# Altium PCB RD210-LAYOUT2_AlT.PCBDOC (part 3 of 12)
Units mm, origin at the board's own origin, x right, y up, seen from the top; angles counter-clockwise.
Board outline 250 x 123 mm, 4 copper layers (TOP, Mid-Layer 1, Mid-Layer 2, BOTTOM), stack 0.711 mm thick; 1043 components, 659 nets, 2786 pads, 1228 vias.
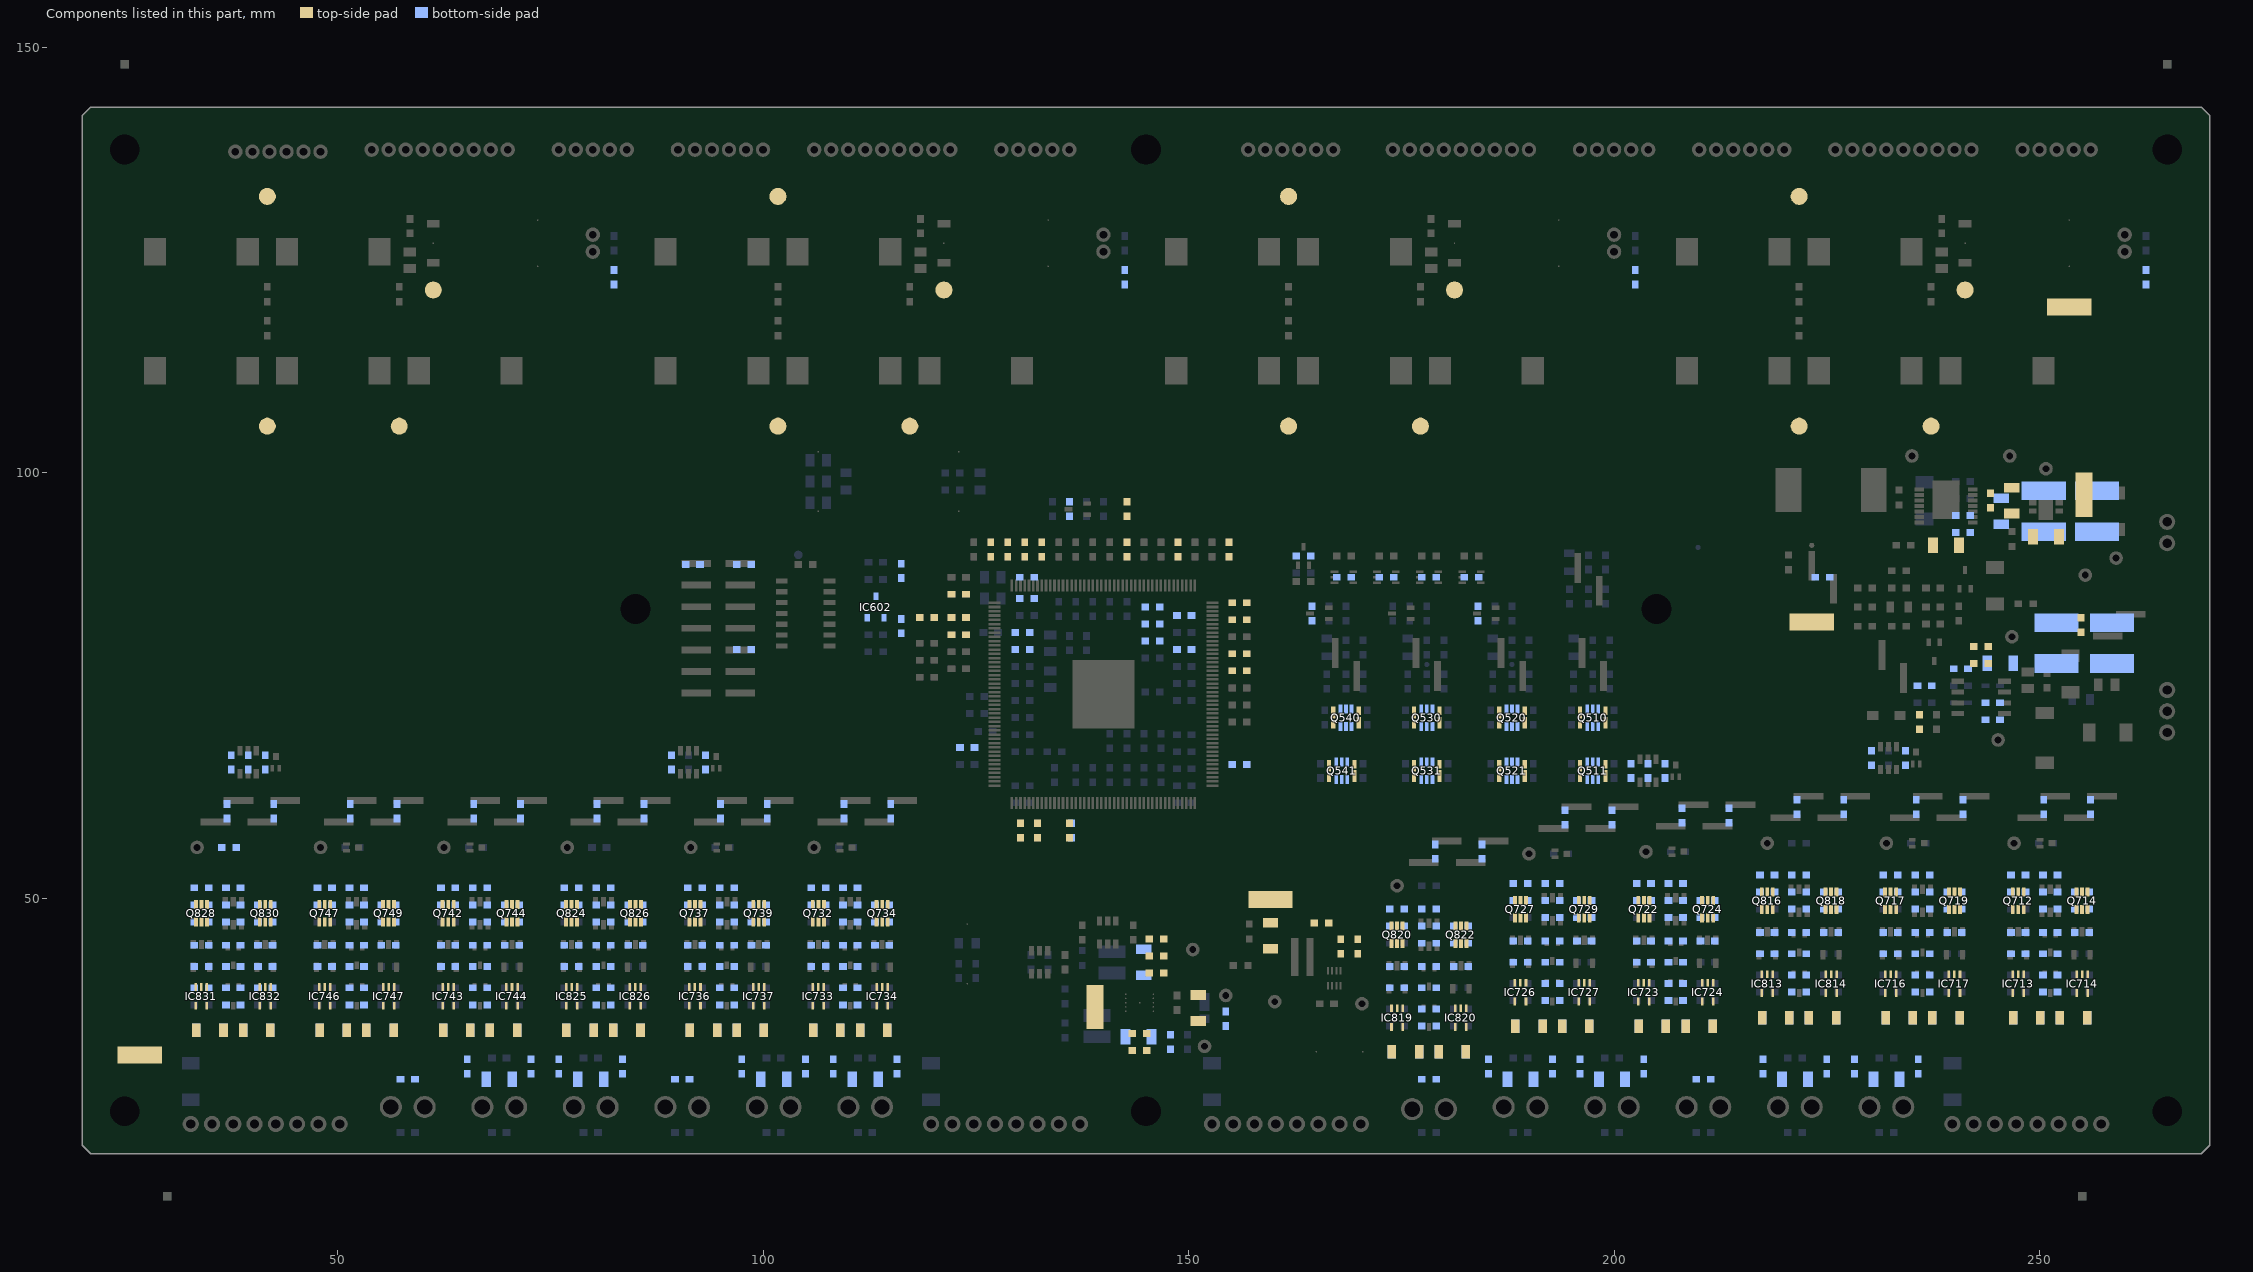
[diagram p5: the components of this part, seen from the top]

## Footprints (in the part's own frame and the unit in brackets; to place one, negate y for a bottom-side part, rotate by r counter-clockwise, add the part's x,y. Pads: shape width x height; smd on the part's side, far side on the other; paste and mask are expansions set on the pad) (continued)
_CGA3E2X7R1H104K080AA_+57 [mm] "KC00080BKP"
  rect 0.9x0.8 smd paste-0.9 mask+0: 1(0.85,0) 2(-0.85,0)
_CGA3E2X7R1H104K080AA_+58 [mm] "KC00080BKP"
  rect 0.9x0.8 smd paste-0.9 mask+0: 1(0.85,0) 2(-0.85,0)
_CGA3E2X7R1H104K080AA_+59 [mm] "KC00080BKP"
  rect 0.9x0.8 smd paste-0.9 mask+0: 1(0.85,0) 2(-0.85,0)
_CGA3E2X7R1H104K080AA_+60 [mm] "KC00080BKP"
  rect 0.9x0.8 smd paste-0.9 mask+0: 1(0.85,0) 2(-0.85,0)
_CGA3E2X7R1H104K080AA_+61 [mm] "KC00080BKP"
  rect 0.9x0.8 smd paste-0.9 mask+0: 1(0.85,0) 2(-0.85,0)
_CGA3E2X7R1H104K080AA_+62 [mm] "KC00080BKP"
  rect 0.9x0.8 smd paste-0.9 mask+0: 1(0.85,0) 2(-0.85,0)
_CGA3E2X7R1H104K080AA_+63 [mm] "KC00080BKP"
  rect 0.9x0.8 smd paste-0.9 mask+0: 1(0.85,0) 2(-0.85,0)
_CGA5H2C0G1H473J115AA_ [mm] "KC00080BKP"
  rect 1.15x1.8 smd paste-1.8 mask+0: 1(1.525,0) 2(-1.525,0)
_CGA5H2C0G1H473J115AA_+1 [mm] "KC00080BKP"
  rect 1.15x1.8 smd paste-1.8 mask+0: 1(1.525,0) 2(-1.525,0)
_CGA5H2C0G1H473J115AA_+2 [mm] "KC00080BKP"
  rect 1.15x1.8 smd paste-1.8 mask+0: 1(1.525,0) 2(-1.525,0)
_CGA5H2C0G1H473J115AA_+3 [mm] "KC00080BKP"
  rect 1.15x1.8 smd paste-1.8 mask+0: 1(1.525,0) 2(-1.525,0)
_CGA5H2C0G1H473J115AA_+4 [mm] "KC00080BKP"
  rect 1.15x1.8 smd paste-1.8 mask+0: 1(1.525,0) 2(-1.525,0)
_CGA5H2C0G1H473J115AA_+5 [mm] "KC00080BKP"
  rect 1.15x1.8 smd paste-1.8 mask+0: 1(1.525,0) 2(-1.525,0)
_CGA5H2C0G1H473J115AA_+6 [mm] "KC00080BKP"
  rect 1.15x1.8 smd paste-1.8 mask+0: 1(1.525,0) 2(-1.525,0)
_CGA5H2C0G1H473J115AA_+7 [mm] "KC00080BKP"
  rect 1.15x1.8 smd paste-1.8 mask+0: 1(1.525,0) 2(-1.525,0)
_CGA5L1X7R0J226M160AC_ [mm] "KC00080BKP"
  rect 1.15x1.8 smd paste-1.8 mask+0: 1(1.525,0) 2(-1.525,0)
_CGA5L1X7R0J226M160AC_+1 [mm] "KC00080BKP"
  rect 1.15x1.8 smd paste-1.8 mask+0: 1(1.525,0) 2(-1.525,0)
_CGA5L1X7R0J226M160AC_+2 [mm] "KC00080BKP"
  rect 1.15x1.8 smd paste-1.8 mask+0: 1(-1.525,0) 2(1.525,0)
_CGA5L1X7R1H106K160AC_ [mm] "KC00080BKP"
  rect 1.15x1.8 smd paste-1.8 mask+0: 1(-1.525,0) 2(1.525,0)
_CGA5L1X7R1H106K160AC_+1 [mm] "KC00080BKP"
  rect 1.15x1.8 smd paste-1.8 mask+0: 1(-1.525,0) 2(1.525,0)
_CGA5L1X7R1H106K160AC_+2 [mm] "KC00080BKP"
  rect 1.15x1.8 smd paste-1.8 mask+0: 1(1.525,0) 2(-1.525,0)
_CGA5L1X7R1H106K160AC_+3 [mm] "KC00080BKP"
  rect 1.15x1.8 smd paste-1.8 mask+0: 1(-1.525,0) 2(1.525,0)
_CGA5L2X7R2A104K160AA_ [mm] "KC00080BKP"
  rect 1.15x1.8 smd paste-1.8 mask+0: 1(-1.525,0) 2(1.525,0)
_CGA5L2X7R2A104K160AA_+1 [mm] "KC00080BKP"
  rect 1.15x1.8 smd paste-1.8 mask+0: 1(1.525,0) 2(-1.525,0)
_CKG57NX7S2A226M500JJ_ [mm] "KC00080BKP"
  rect 2.2x5.2 smd paste-5.2 mask+0: 1(2.4,0) 2(-2.4,0)
_CKG57NX7S2A226M500JJ_+1 [mm] "KC00080BKP"
  rect 2.2x5.2 smd paste-5.2 mask+0: 1(2.4,0) 2(-2.4,0)
_CKG57NX7S2A226M500JJ_+2 [mm] "KC00080BKP"
  rect 2.2x5.2 smd paste-5.2 mask+0: 1(2.4,0) 2(-2.4,0)
_CKG57NX7S2A226M500JJ_+3 [mm] "KC00080BKP"
  rect 2.2x5.2 smd paste-5.2 mask+0: 1(2.4,0) 2(-2.4,0)
_Direct_In_PAD-D2_ [mm] "KC00080BKP"
  round 2 smd paste-2 mask+0: 1(0,0)
_Direct_In_PAD-D2_+1 [mm] "KC00080BKP"
  round 2 smd paste-2 mask+0: 1(0,0)
_Direct_In_PAD-D2_+2 [mm] "KC00080BKP"
  round 2 smd paste-2 mask+0: 1(0,0)
_Direct_In_PAD-D2_+3 [mm] "KC00080BKP"
  round 2 smd paste-2 mask+0: 1(0,0)
_Direct_In_PAD-D2_+4 [mm] "KC00080BKP"
  round 2 smd paste-2 mask+0: 1(0,0)
_Direct_In_PAD-D2_+5 [mm] "KC00080BKP"
  round 2 smd paste-2 mask+0: 1(0,0)
_Direct_In_PAD-D2_+6 [mm] "KC00080BKP"
  round 2 smd paste-2 mask+0: 1(0,0)
_Direct_In_PAD-D2_+7 [mm] "KC00080BKP"
  round 2 smd paste-2 mask+0: 1(0,0)
_Direct_In_PAD-D2_+8 [mm] "KC00080BKP"
  round 2 smd paste-2 mask+0: 1(0,0)
_Direct_In_PAD-D2_+9 [mm] "KC00080BKP"
  round 2 smd paste-2 mask+0: 1(0,0)
_Direct_In_PAD-D2_+10 [mm] "KC00080BKP"
  round 2 smd paste-2 mask+0: 1(0,0)
_Direct_In_PAD-D2_+11 [mm] "KC00080BKP"
  round 2 smd paste-2 mask+0: 1(0,0)
_Direct_In_PAD-D2_+12 [mm] "KC00080BKP"
  round 2 smd paste-2 mask+0: 1(0,0)
_Direct_In_PAD-D2_+13 [mm] "KC00080BKP"
  round 2 smd paste-2 mask+0: 1(0,0)
_Direct_In_PAD-D2_+14 [mm] "KC00080BKP"
  round 2 smd paste-2 mask+0: 1(0,0)
_Direct_In_PAD-D2_+15 [mm] "KC00080BKP"
  round 2 smd paste-2 mask+0: 1(0,0)
_HW-1-S_ [mm] "KC00080BKP"
  rect 5.2x2 smd paste-5.2 mask+0: 1(0,0)
_HW-1-S_+1 [mm] "KC00080BKP"
  rect 5.2x2 smd paste-5.2 mask+0: 1(0,0)
_HW-1-S_+2 [mm] "KC00080BKP"
  rect 5.2x2 smd paste-5.2 mask+0: 1(0,0)
_HW-1-S_+3 [mm] "KC00080BKP"
  rect 5.2x2 smd paste-5.2 mask+0: 1(0,0)
_HW-1-S_+4 [mm] "KC00080BKP"
  rect 5.2x2 smd paste-5.2 mask+0: 1(0,0)
_HW-1-S_+5 [mm] "KC00080BKP"
  rect 5.2x2 smd paste-5.2 mask+0: 1(0,0)
_INA290A2QDCKRQ1_ [mm] "KC00080BKP"
  rect 0.3x0.9 smd paste-0.9 mask+0: 1(-0.65,-1.1) 2(0,-1.1) 3(0.65,-1.1) 4(0.65,1.1) 5(-0.65,1.1)
_INA290A2QDCKRQ1_+1 [mm] "KC00080BKP"
  rect 0.3x0.9 smd paste-0.9 mask+0: 1(-0.65,-1.1) 2(0,-1.1) 3(0.65,-1.1) 4(0.65,1.1) 5(-0.65,1.1)
_INA290A2QDCKRQ1_+2 [mm] "KC00080BKP"
  rect 0.3x0.9 smd paste-0.9 mask+0: 1(-0.65,-1.1) 2(0,-1.1) 3(0.65,-1.1) 4(0.65,1.1) 5(-0.65,1.1)
_INA290A2QDCKRQ1_+3 [mm] "KC00080BKP"
  rect 0.3x0.9 smd paste-0.9 mask+0: 1(-0.65,-1.1) 2(0,-1.1) 3(0.65,-1.1) 4(0.65,1.1) 5(-0.65,1.1)
_INA290A2QDCKRQ1_+4 [mm] "KC00080BKP"
  rect 0.3x0.9 smd paste-0.9 mask+0: 1(-0.65,-1.1) 2(0,-1.1) 3(0.65,-1.1) 4(0.65,1.1) 5(-0.65,1.1)
_INA290A2QDCKRQ1_+5 [mm] "KC00080BKP"
  rect 0.3x0.9 smd paste-0.9 mask+0: 1(-0.65,-1.1) 2(0,-1.1) 3(0.65,-1.1) 4(0.65,1.1) 5(-0.65,1.1)
_INA290A2QDCKRQ1_+6 [mm] "KC00080BKP"
  rect 0.3x0.9 smd paste-0.9 mask+0: 1(-0.65,-1.1) 2(0,-1.1) 3(0.65,-1.1) 4(0.65,1.1) 5(-0.65,1.1)
_INA290A2QDCKRQ1_+7 [mm] "KC00080BKP"
  rect 0.3x0.9 smd paste-0.9 mask+0: 1(-0.65,-1.1) 2(0,-1.1) 3(0.65,-1.1) 4(0.65,1.1) 5(-0.65,1.1)
_INA290A2QDCKRQ1_+8 [mm] "KC00080BKP"
  rect 0.3x0.9 smd paste-0.9 mask+0: 1(-0.65,-1.1) 2(0,-1.1) 3(0.65,-1.1) 4(0.65,1.1) 5(-0.65,1.1)
_INA290A2QDCKRQ1_+9 [mm] "KC00080BKP"
  rect 0.3x0.9 smd paste-0.9 mask+0: 1(-0.65,-1.1) 2(0,-1.1) 3(0.65,-1.1) 4(0.65,1.1) 5(-0.65,1.1)
_INA290A2QDCKRQ1_+10 [mm] "KC00080BKP"
  rect 0.3x0.9 smd paste-0.9 mask+0: 1(-0.65,-1.1) 2(0,-1.1) 3(0.65,-1.1) 4(0.65,1.1) 5(-0.65,1.1)
_INA290A2QDCKRQ1_+11 [mm] "KC00080BKP"
  rect 0.3x0.9 smd paste-0.9 mask+0: 1(-0.65,-1.1) 2(0,-1.1) 3(0.65,-1.1) 4(0.65,1.1) 5(-0.65,1.1)
_INA290A2QDCKRQ1_+12 [mm] "KC00080BKP"
  rect 0.3x0.9 smd paste-0.9 mask+0: 1(-0.65,-1.1) 2(0,-1.1) 3(0.65,-1.1) 4(0.65,1.1) 5(-0.65,1.1)
_INA290A2QDCKRQ1_+13 [mm] "KC00080BKP"
  rect 0.3x0.9 smd paste-0.9 mask+0: 1(-0.65,-1.1) 2(0,-1.1) 3(0.65,-1.1) 4(0.65,1.1) 5(-0.65,1.1)
_INA290A2QDCKRQ1_+14 [mm] "KC00080BKP"
  rect 0.3x0.9 smd paste-0.9 mask+0: 1(-0.65,-1.1) 2(0,-1.1) 3(0.65,-1.1) 4(0.65,1.1) 5(-0.65,1.1)
_INA290A2QDCKRQ1_+15 [mm] "KC00080BKP"
  rect 0.3x0.9 smd paste-0.9 mask+0: 1(-0.65,-1.1) 2(0,-1.1) 3(0.65,-1.1) 4(0.65,1.1) 5(-0.65,1.1)
_INA290A2QDCKRQ1_+16 [mm] "KC00080BKP"
  rect 0.3x0.9 smd paste-0.9 mask+0: 1(-0.65,-1.1) 2(0,-1.1) 3(0.65,-1.1) 4(0.65,1.1) 5(-0.65,1.1)
_INA290A2QDCKRQ1_+17 [mm] "KC00080BKP"
  rect 0.3x0.9 smd paste-0.9 mask+0: 1(-0.65,-1.1) 2(0,-1.1) 3(0.65,-1.1) 4(0.65,1.1) 5(-0.65,1.1)
_INA290A2QDCKRQ1_+18 [mm] "KC00080BKP"
  rect 0.3x0.9 smd paste-0.9 mask+0: 1(-0.65,-1.1) 2(0,-1.1) 3(0.65,-1.1) 4(0.65,1.1) 5(-0.65,1.1)
_INA290A2QDCKRQ1_+19 [mm] "KC00080BKP"
  rect 0.3x0.9 smd paste-0.9 mask+0: 1(-0.65,-1.1) 2(0,-1.1) 3(0.65,-1.1) 4(0.65,1.1) 5(-0.65,1.1)
_INA290A2QDCKRQ1_+20 [mm] "KC00080BKP"
  rect 0.3x0.9 smd paste-0.9 mask+0: 1(-0.65,-1.1) 2(0,-1.1) 3(0.65,-1.1) 4(0.65,1.1) 5(-0.65,1.1)
_INA290A2QDCKRQ1_+21 [mm] "KC00080BKP"
  rect 0.3x0.9 smd paste-0.9 mask+0: 1(-0.65,-1.1) 2(0,-1.1) 3(0.65,-1.1) 4(0.65,1.1) 5(-0.65,1.1)
_INA290A2QDCKRQ1_+22 [mm] "KC00080BKP"
  rect 0.3x0.9 smd paste-0.9 mask+0: 1(-0.65,-1.1) 2(0,-1.1) 3(0.65,-1.1) 4(0.65,1.1) 5(-0.65,1.1)
_INA290A2QDCKRQ1_+23 [mm] "KC00080BKP"
  rect 0.3x0.9 smd paste-0.9 mask+0: 1(-0.65,-1.1) 2(0,-1.1) 3(0.65,-1.1) 4(0.65,1.1) 5(-0.65,1.1)
_KB_DELPS2.12_ [mm] "KC00080BKP"
  rect 1.4x0.5 smd paste-1.4 mask+0: 1(-0.6,0)
  rect 1x0.5 smd paste-1 mask+0: 2(0.8,0)
_KB_DELPS2.12_+1 [mm] "KC00080BKP"
  rect 1.4x0.5 smd paste-1.4 mask+0: 1(-0.6,0)
  rect 1x0.5 smd paste-1 mask+0: 2(0.8,0)
_KB_DELPS2.12_+2 [mm] "KC00080BKP"
  rect 1.4x0.5 smd paste-1.4 mask+0: 1(-0.6,0)
  rect 1x0.5 smd paste-1 mask+0: 2(0.8,0)
_KB_DELPS2.12_+3 [mm] "KC00080BKP"
  rect 1.4x0.5 smd paste-1.4 mask+0: 1(-0.6,0)
  rect 1x0.5 smd paste-1 mask+0: 2(0.8,0)
_KS_DELPS1.22_ [mm] "KC00080BKP"
  rect 1.4x0.5 smd paste-1.4 mask+0: 1(-0.6,0)
  rect 1x0.5 smd paste-1 mask+0: 2(0.8,0)
_KS_DELPS1.22_+1 [mm] "KC00080BKP"
  rect 1.4x0.5 smd paste-1.4 mask+0: 1(-0.6,0)
  rect 1x0.5 smd paste-1 mask+0: 2(0.8,0)
_KS_DELPS1.22_+2 [mm] "KC00080BKP"
  rect 1.4x0.5 smd paste-1.4 mask+0: 1(-0.6,0)
  rect 1x0.5 smd paste-1 mask+0: 2(0.8,0)
_KS_DELPS1.22_+3 [mm] "KC00080BKP"
  rect 1.4x0.5 smd paste-1.4 mask+0: 1(-0.6,0)
  rect 1x0.5 smd paste-1 mask+0: 2(0.8,0)
_KT_DELQS1.12_ [mm] "KC00080BKP"
  rect 1.4x0.5 smd paste-1.4 mask+0: 1(-0.6,0)
  rect 1x0.5 smd paste-1 mask+0: 2(0.8,0)
_KT_DELQS1.12_+1 [mm] "KC00080BKP"
  rect 1.4x0.5 smd paste-1.4 mask+0: 1(-0.6,0)
  rect 1x0.5 smd paste-1 mask+0: 2(0.8,0)
_KT_DELQS1.12_+2 [mm] "KC00080BKP"
  rect 1.4x0.5 smd paste-1.4 mask+0: 1(-0.6,0)
  rect 1x0.5 smd paste-1 mask+0: 2(0.8,0)
_KT_DELQS1.12_+3 [mm] "KC00080BKP"
  rect 1.4x0.5 smd paste-1.4 mask+0: 1(-0.6,0)
  rect 1x0.5 smd paste-1 mask+0: 2(0.8,0)
_KT_DELQS1.12_+4 [mm] "KC00080BKP"
  rect 1.4x0.5 smd paste-1.4 mask+0: 1(-0.6,0)
  rect 1x0.5 smd paste-1 mask+0: 2(0.8,0)
_KT_DELQS1.12_+5 [mm] "KC00080BKP"
  rect 1.4x0.5 smd paste-1.4 mask+0: 1(-0.6,0)
  rect 1x0.5 smd paste-1 mask+0: 2(0.8,0)
_KT_DELQS1.12_+6 [mm] "KC00080BKP"
  rect 1.4x0.5 smd paste-1.4 mask+0: 1(-0.6,0)
  rect 1x0.5 smd paste-1 mask+0: 2(0.8,0)
_KT_DELQS1.12_+7 [mm] "KC00080BKP"
  rect 1.4x0.5 smd paste-1.4 mask+0: 1(-0.6,0)
  rect 1x0.5 smd paste-1 mask+0: 2(0.8,0)
_LM4040QCEM3-3.0_ [mm] "KC00080BKP"
  rect 0.6x0.9 smd paste-0.9 mask+0: 1(0.95,1.25) 2(-1,1.25) 3(0,-1.25)
_RK73B1JTTD1R0J_ [mm] "KC00080BKP"
  rect 0.9x0.8 smd paste-0.9 mask+0: 1(0.85,0) 2(-0.85,0)
_RK73B1JTTD1R0J_+1 [mm] "KC00080BKP"
  rect 0.9x0.8 smd paste-0.9 mask+0: 1(0.85,0) 2(-0.85,0)
_RK73B1JTTD1R0J_+2 [mm] "KC00080BKP"
  rect 0.9x0.8 smd paste-0.9 mask+0: 1(0.85,0) 2(-0.85,0)
_RK73B1JTTD1R0J_+3 [mm] "KC00080BKP"
  rect 0.9x0.8 smd paste-0.9 mask+0: 1(0.85,0) 2(-0.85,0)
_RK73B1JTTD103J_ [mm] "KC00080BKP"
  rect 0.9x0.8 smd paste-0.9 mask+0: 1(0.85,0) 2(-0.85,0)
_RK73B1JTTD103J_+1 [mm] "KC00080BKP"
  rect 0.9x0.8 smd paste-0.9 mask+0: 1(0.85,0) 2(-0.85,0)
_RK73B1JTTD103J_+2 [mm] "KC00080BKP"
  rect 0.9x0.8 smd paste-0.9 mask+0: 1(0.85,0) 2(-0.85,0)
_RK73B1JTTD103J_+3 [mm] "KC00080BKP"
  rect 0.9x0.8 smd paste-0.9 mask+0: 1(0.85,0) 2(-0.85,0)
_RK73B1JTTD103J_+4 [mm] "KC00080BKP"
  rect 0.9x0.8 smd paste-0.9 mask+0: 1(0.85,0) 2(-0.85,0)
_RK73B1JTTD103J_+5 [mm] "KC00080BKP"
  rect 0.9x0.8 smd paste-0.9 mask+0: 1(0.85,0) 2(-0.85,0)
_RK73B1JTTD103J_+6 [mm] "KC00080BKP"
  rect 0.9x0.8 smd paste-0.9 mask+0: 1(0.85,0) 2(-0.85,0)
_RK73B1JTTD103J_+7 [mm] "KC00080BKP"
  rect 0.9x0.8 smd paste-0.9 mask+0: 1(0.85,0) 2(-0.85,0)
_RK73B1JTTD103J_+8 [mm] "KC00080BKP"
  rect 0.9x0.8 smd paste-0.9 mask+0: 1(0.85,0) 2(-0.85,0)
_RK73B1JTTD103J_+9 [mm] "KC00080BKP"
  rect 0.9x0.8 smd paste-0.9 mask+0: 1(0.85,0) 2(-0.85,0)
_RK73B1JTTD103J_+10 [mm] "KC00080BKP"
  rect 0.9x0.8 smd paste-0.9 mask+0: 1(0.85,0) 2(-0.85,0)
_RK73B1JTTD103J_+11 [mm] "KC00080BKP"
  rect 0.9x0.8 smd paste-0.9 mask+0: 1(0.85,0) 2(-0.85,0)
_RK73B1JTTD103J_+12 [mm] "KC00080BKP"
  rect 0.9x0.8 smd paste-0.9 mask+0: 1(0.85,0) 2(-0.85,0)
_RK73B1JTTD103J_+13 [mm] "KC00080BKP"
  rect 0.9x0.8 smd paste-0.9 mask+0: 1(0.85,0) 2(-0.85,0)
_RK73B1JTTD103J_+14 [mm] "KC00080BKP"
  rect 0.9x0.8 smd paste-0.9 mask+0: 1(0.85,0) 2(-0.85,0)
_RK73B1JTTD103J_+15 [mm] "KC00080BKP"
  rect 0.9x0.8 smd paste-0.9 mask+0: 1(0.85,0) 2(-0.85,0)
_RK73B1JTTD103J_+16 [mm] "KC00080BKP"
  rect 0.9x0.8 smd paste-0.9 mask+0: 1(0.85,0) 2(-0.85,0)
_RK73B1JTTD103J_+17 [mm] "KC00080BKP"
  rect 0.9x0.8 smd paste-0.9 mask+0: 1(0.85,0) 2(-0.85,0)
_RK73B1JTTD103J_+18 [mm] "KC00080BKP"
  rect 0.9x0.8 smd paste-0.9 mask+0: 1(0.85,0) 2(-0.85,0)
_RK73B1JTTD103J_+19 [mm] "KC00080BKP"
  rect 0.9x0.8 smd paste-0.9 mask+0: 1(0.85,0) 2(-0.85,0)
_RK73B1JTTD103J_+20 [mm] "KC00080BKP"
  rect 0.9x0.8 smd paste-0.9 mask+0: 1(0.85,0) 2(-0.85,0)
_RK73B1JTTD103J_+21 [mm] "KC00080BKP"
  rect 0.9x0.8 smd paste-0.9 mask+0: 1(0.85,0) 2(-0.85,0)
_RK73B1JTTD103J_+22 [mm] "KC00080BKP"
  rect 0.9x0.8 smd paste-0.9 mask+0: 1(0.85,0) 2(-0.85,0)
_RK73B1JTTD103J_+23 [mm] "KC00080BKP"
  rect 0.9x0.8 smd paste-0.9 mask+0: 1(0.85,0) 2(-0.85,0)
_RK73B2BTTD100J_ [mm] "KC00080BKP"
  rect 1x1.6 smd paste-1.6 mask+0: 1(-1.6,0) 2(1.6,0)
_RK73B2BTTD100J_+1 [mm] "KC00080BKP"
  rect 1x1.6 smd paste-1.6 mask+0: 1(-1.6,0) 2(1.6,0)
_RK73B2BTTD100J_+2 [mm] "KC00080BKP"
  rect 1x1.6 smd paste-1.6 mask+0: 1(-1.6,0) 2(1.6,0)
_RK73B2BTTD100J_+3 [mm] "KC00080BKP"
  rect 1x1.6 smd paste-1.6 mask+0: 1(-1.6,0) 2(1.6,0)
_RK73B2BTTD100J_+4 [mm] "KC00080BKP"
  rect 1x1.6 smd paste-1.6 mask+0: 1(-1.6,0) 2(1.6,0)
_RK73B2BTTD100J_+5 [mm] "KC00080BKP"
  rect 1x1.6 smd paste-1.6 mask+0: 1(-1.6,0) 2(1.6,0)
_RK73B2BTTD100J_+6 [mm] "KC00080BKP"
  rect 1x1.6 smd paste-1.6 mask+0: 1(-1.6,0) 2(1.6,0)
_RK73B2BTTD100J_+7 [mm] "KC00080BKP"
  rect 1x1.6 smd paste-1.6 mask+0: 1(-1.6,0) 2(1.6,0)
_RK73B2BTTD100J_+8 [mm] "KC00080BKP"
  rect 1x1.6 smd paste-1.6 mask+0: 1(-1.6,0) 2(1.6,0)
_RK73B2BTTD100J_+9 [mm] "KC00080BKP"
  rect 1x1.6 smd paste-1.6 mask+0: 1(-1.6,0) 2(1.6,0)
_RK73B2BTTD100J_+10 [mm] "KC00080BKP"
  rect 1x1.6 smd paste-1.6 mask+0: 1(-1.6,0) 2(1.6,0)
_RK73B2BTTD100J_+11 [mm] "KC00080BKP"
  rect 1x1.6 smd paste-1.6 mask+0: 1(-1.6,0) 2(1.6,0)
_RK73B2BTTD100J_+12 [mm] "KC00080BKP"
  rect 1x1.6 smd paste-1.6 mask+0: 1(-1.6,0) 2(1.6,0)
_RK73B2BTTD100J_+13 [mm] "KC00080BKP"
  rect 1x1.6 smd paste-1.6 mask+0: 1(-1.6,0) 2(1.6,0)
_RK73B2BTTD100J_+14 [mm] "KC00080BKP"
  rect 1x1.6 smd paste-1.6 mask+0: 1(-1.6,0) 2(1.6,0)
_RK73B2BTTD100J_+15 [mm] "KC00080BKP"
  rect 1x1.6 smd paste-1.6 mask+0: 1(-1.6,0) 2(1.6,0)
_RK73B2BTTD100J_+16 [mm] "KC00080BKP"
  rect 1x1.6 smd paste-1.6 mask+0: 1(-1.6,0) 2(1.6,0)
_RK73B2BTTD100J_+17 [mm] "KC00080BKP"
  rect 1x1.6 smd paste-1.6 mask+0: 1(-1.6,0) 2(1.6,0)
_RK73B2BTTD100J_+18 [mm] "KC00080BKP"
  rect 1x1.6 smd paste-1.6 mask+0: 1(1.6,0) 2(-1.6,0)
_RK73B2BTTD100J_+19 [mm] "KC00080BKP"
  rect 1x1.6 smd paste-1.6 mask+0: 1(1.6,0) 2(-1.6,0)
_RK73B2BTTD100J_+20 [mm] "KC00080BKP"
  rect 1x1.6 smd paste-1.6 mask+0: 1(-1.6,0) 2(1.6,0)
_RK73B2BTTD100J_+21 [mm] "KC00080BKP"
  rect 1x1.6 smd paste-1.6 mask+0: 1(-1.6,0) 2(1.6,0)
_RK73B2BTTD100J_+22 [mm] "KC00080BKP"
  rect 1x1.6 smd paste-1.6 mask+0: 1(1.6,0) 2(-1.6,0)
_RK73B2BTTD100J_+23 [mm] "KC00080BKP"
  rect 1x1.6 smd paste-1.6 mask+0: 1(1.6,0) 2(-1.6,0)
_RK73B2BTTD100J_+24 [mm] "KC00080BKP"
  rect 1x1.6 smd paste-1.6 mask+0: 1(1.6,0) 2(-1.6,0)
_RK73B2BTTD100J_+25 [mm] "KC00080BKP"
  rect 1x1.6 smd paste-1.6 mask+0: 1(1.6,0) 2(-1.6,0)
_RK73B2BTTD100J_+26 [mm] "KC00080BKP"
  rect 1x1.6 smd paste-1.6 mask+0: 1(1.6,0) 2(-1.6,0)
_RK73B2BTTD100J_+27 [mm] "KC00080BKP"
  rect 1x1.6 smd paste-1.6 mask+0: 1(1.6,0) 2(-1.6,0)
_RK73B2BTTD100J_+28 [mm] "KC00080BKP"
  rect 1x1.6 smd paste-1.6 mask+0: 1(1.6,0) 2(-1.6,0)
_RK73B2BTTD100J_+29 [mm] "KC00080BKP"
  rect 1x1.6 smd paste-1.6 mask+0: 1(-1.6,0) 2(1.6,0)
_RK73B2BTTD100J_+30 [mm] "KC00080BKP"
  rect 1x1.6 smd paste-1.6 mask+0: 1(1.6,0) 2(-1.6,0)
_RK73B2BTTD100J_+31 [mm] "KC00080BKP"
  rect 1x1.6 smd paste-1.6 mask+0: 1(1.6,0) 2(-1.6,0)
_RK73B2BTTD100J_+32 [mm] "KC00080BKP"
  rect 1x1.6 smd paste-1.6 mask+0: 1(1.6,0) 2(-1.6,0)
_RK73B2BTTD100J_+33 [mm] "KC00080BKP"
  rect 1x1.6 smd paste-1.6 mask+0: 1(1.6,0) 2(-1.6,0)
_RK73B2BTTD100J_+34 [mm] "KC00080BKP"
  rect 1x1.6 smd paste-1.6 mask+0: 1(1.6,0) 2(-1.6,0)
_RK73B2BTTD100J_+35 [mm] "KC00080BKP"
  rect 1x1.6 smd paste-1.6 mask+0: 1(1.6,0) 2(-1.6,0)
_RK73B2BTTD100J_+36 [mm] "KC00080BKP"
  rect 1x1.6 smd paste-1.6 mask+0: 1(1.6,0) 2(-1.6,0)
_RK73B2BTTD100J_+37 [mm] "KC00080BKP"
  rect 1x1.6 smd paste-1.6 mask+0: 1(1.6,0) 2(-1.6,0)
_RK73B2BTTD100J_+38 [mm] "KC00080BKP"
  rect 1x1.6 smd paste-1.6 mask+0: 1(1.6,0) 2(-1.6,0)
_RK73B2BTTD100J_+39 [mm] "KC00080BKP"
  rect 1x1.6 smd paste-1.6 mask+0: 1(1.6,0) 2(-1.6,0)
_RK73B2BTTD100J_+40 [mm] "KC00080BKP"
  rect 1x1.6 smd paste-1.6 mask+0: 1(1.6,0) 2(-1.6,0)
_RK73B2BTTD100J_+41 [mm] "KC00080BKP"
  rect 1x1.6 smd paste-1.6 mask+0: 1(1.6,0) 2(-1.6,0)
_RK73B2BTTD100J_+42 [mm] "KC00080BKP"
  rect 1x1.6 smd paste-1.6 mask+0: 1(1.6,0) 2(-1.6,0)
_RK73B2BTTD100J_+43 [mm] "KC00080BKP"
  rect 1x1.6 smd paste-1.6 mask+0: 1(1.6,0) 2(-1.6,0)
_RK73B2BTTD100J_+44 [mm] "KC00080BKP"
  rect 1x1.6 smd paste-1.6 mask+0: 1(-1.6,0) 2(1.6,0)
_RK73B2BTTD100J_+45 [mm] "KC00080BKP"
  rect 1x1.6 smd paste-1.6 mask+0: 1(1.6,0) 2(-1.6,0)
_RK73B2BTTD100J_+46 [mm] "KC00080BKP"
  rect 1x1.6 smd paste-1.6 mask+0: 1(-1.6,0) 2(1.6,0)
_RK73B2BTTD100J_+47 [mm] "KC00080BKP"
  rect 1x1.6 smd paste-1.6 mask+0: 1(-1.6,0) 2(1.6,0)
_RK73G1JTTD10R0D_ [mm] "KC00080BKP"
  rect 0.9x0.8 smd paste-0.9 mask+0: 1(-0.85,0) 2(0.85,0)
_RK73G1JTTD10R0D_+1 [mm] "KC00080BKP"
  rect 0.9x0.8 smd paste-0.9 mask+0: 1(0.85,0) 2(-0.85,0)
_RK73H1JTTD10R0F_ [mm] "KC00080BKP"
  rect 0.9x0.8 smd paste-0.9 mask+0: 1(0.85,0) 2(-0.85,0)
_RK73H1JTTD10R0F_+1 [mm] "KC00080BKP"
  rect 0.9x0.8 smd paste-0.9 mask+0: 1(0.85,0) 2(-0.85,0)
_RK73H1JTTD10R0F_+2 [mm] "KC00080BKP"
  rect 0.9x0.8 smd paste-0.9 mask+0: 1(0.85,0) 2(-0.85,0)
_RK73H1JTTD10R0F_+3 [mm] "KC00080BKP"
  rect 0.9x0.8 smd paste-0.9 mask+0: 1(0.85,0) 2(-0.85,0)
_RK73H1JTTD10R0F_+4 [mm] "KC00080BKP"
  rect 0.9x0.8 smd paste-0.9 mask+0: 1(0.85,0) 2(-0.85,0)
_RK73H1JTTD10R0F_+5 [mm] "KC00080BKP"
  rect 0.9x0.8 smd paste-0.9 mask+0: 1(0.85,0) 2(-0.85,0)
_RK73H1JTTD10R0F_+6 [mm] "KC00080BKP"
  rect 0.9x0.8 smd paste-0.9 mask+0: 1(0.85,0) 2(-0.85,0)
_RK73H1JTTD10R0F_+7 [mm] "KC00080BKP"
  rect 0.9x0.8 smd paste-0.9 mask+0: 1(0.85,0) 2(-0.85,0)
_RK73H1JTTD10R0F_+8 [mm] "KC00080BKP"
  rect 0.9x0.8 smd paste-0.9 mask+0: 1(0.85,0) 2(-0.85,0)
_RK73H1JTTD10R0F_+9 [mm] "KC00080BKP"
  rect 0.9x0.8 smd paste-0.9 mask+0: 1(0.85,0) 2(-0.85,0)
_RK73H1JTTD10R0F_+10 [mm] "KC00080BKP"
  rect 0.9x0.8 smd paste-0.9 mask+0: 1(0.85,0) 2(-0.85,0)
_RK73H1JTTD10R0F_+11 [mm] "KC00080BKP"
  rect 0.9x0.8 smd paste-0.9 mask+0: 1(0.85,0) 2(-0.85,0)
_RK73H1JTTD47R0F_ [mm] "KC00080BKP"
  rect 0.9x0.8 smd paste-0.9 mask+0: 1(0.85,0) 2(-0.85,0)
_RK73H1JTTD47R0F_+1 [mm] "KC00080BKP"
  rect 0.9x0.8 smd paste-0.9 mask+0: 1(0.85,0) 2(-0.85,0)
_RK73H1JTTD47R0F_+2 [mm] "KC00080BKP"
  rect 0.9x0.8 smd paste-0.9 mask+0: 1(0.85,0) 2(-0.85,0)
_RK73H1JTTD47R0F_+3 [mm] "KC00080BKP"
  rect 0.9x0.8 smd paste-0.9 mask+0: 1(0.85,0) 2(-0.85,0)
_RK73H1JTTD47R0F_+4 [mm] "KC00080BKP"
  rect 0.9x0.8 smd paste-0.9 mask+0: 1(0.85,0) 2(-0.85,0)
_RK73H1JTTD47R0F_+5 [mm] "KC00080BKP"
  rect 0.9x0.8 smd paste-0.9 mask+0: 1(0.85,0) 2(-0.85,0)
_RK73H1JTTD47R0F_+6 [mm] "KC00080BKP"
  rect 0.9x0.8 smd paste-0.9 mask+0: 1(0.85,0) 2(-0.85,0)
_RK73H1JTTD47R0F_+7 [mm] "KC00080BKP"
  rect 0.9x0.8 smd paste-0.9 mask+0: 1(0.85,0) 2(-0.85,0)
_RK73H1JTTD47R0F_+8 [mm] "KC00080BKP"
  rect 0.9x0.8 smd paste-0.9 mask+0: 1(0.85,0) 2(-0.85,0)
_RK73H1JTTD47R0F_+9 [mm] "KC00080BKP"
  rect 0.9x0.8 smd paste-0.9 mask+0: 1(0.85,0) 2(-0.85,0)
_RK73H1JTTD47R0F_+10 [mm] "KC00080BKP"
  rect 0.9x0.8 smd paste-0.9 mask+0: 1(0.85,0) 2(-0.85,0)
_RK73H1JTTD47R0F_+11 [mm] "KC00080BKP"
  rect 0.9x0.8 smd paste-0.9 mask+0: 1(0.85,0) 2(-0.85,0)
_RK73H1JTTD47R0F_+12 [mm] "KC00080BKP"
  rect 0.9x0.8 smd paste-0.9 mask+0: 1(0.85,0) 2(-0.85,0)
_RK73H1JTTD47R0F_+13 [mm] "KC00080BKP"
  rect 0.9x0.8 smd paste-0.9 mask+0: 1(0.85,0) 2(-0.85,0)
_RK73H1JTTD47R0F_+14 [mm] "KC00080BKP"
  rect 0.9x0.8 smd paste-0.9 mask+0: 1(0.85,0) 2(-0.85,0)
_RK73H1JTTD47R0F_+15 [mm] "KC00080BKP"
  rect 0.9x0.8 smd paste-0.9 mask+0: 1(0.85,0) 2(-0.85,0)
_RK73H1JTTD47R0F_+16 [mm] "KC00080BKP"
  rect 0.9x0.8 smd paste-0.9 mask+0: 1(0.85,0) 2(-0.85,0)
_RK73H1JTTD47R0F_+17 [mm] "KC00080BKP"
  rect 0.9x0.8 smd paste-0.9 mask+0: 1(0.85,0) 2(-0.85,0)
_RK73H1JTTD47R0F_+18 [mm] "KC00080BKP"
  rect 0.9x0.8 smd paste-0.9 mask+0: 1(0.85,0) 2(-0.85,0)
_RK73H1JTTD47R0F_+19 [mm] "KC00080BKP"
  rect 0.9x0.8 smd paste-0.9 mask+0: 1(0.85,0) 2(-0.85,0)
_RK73H1JTTD47R0F_+20 [mm] "KC00080BKP"
  rect 0.9x0.8 smd paste-0.9 mask+0: 1(0.85,0) 2(-0.85,0)
_RK73H1JTTD47R0F_+21 [mm] "KC00080BKP"
  rect 0.9x0.8 smd paste-0.9 mask+0: 1(0.85,0) 2(-0.85,0)
_RK73H1JTTD47R0F_+22 [mm] "KC00080BKP"
  rect 0.9x0.8 smd paste-0.9 mask+0: 1(0.85,0) 2(-0.85,0)
_RK73H1JTTD47R0F_+23 [mm] "KC00080BKP"
  rect 0.9x0.8 smd paste-0.9 mask+0: 1(0.85,0) 2(-0.85,0)
_RK73H1JTTD47R0F_+24 [mm] "KC00080BKP"
  rect 0.9x0.8 smd paste-0.9 mask+0: 1(0.85,0) 2(-0.85,0)
_RK73H1JTTD47R0F_+25 [mm] "KC00080BKP"
  rect 0.9x0.8 smd paste-0.9 mask+0: 1(0.85,0) 2(-0.85,0)
_RK73H1JTTD47R0F_+26 [mm] "KC00080BKP"
  rect 0.9x0.8 smd paste-0.9 mask+0: 1(0.85,0) 2(-0.85,0)
_RK73H1JTTD47R0F_+27 [mm] "KC00080BKP"
  rect 0.9x0.8 smd paste-0.9 mask+0: 1(0.85,0) 2(-0.85,0)
_RK73H1JTTD47R0F_+28 [mm] "KC00080BKP"
  rect 0.9x0.8 smd paste-0.9 mask+0: 1(0.85,0) 2(-0.85,0)
_RK73H1JTTD47R0F_+29 [mm] "KC00080BKP"
  rect 0.9x0.8 smd paste-0.9 mask+0: 1(0.85,0) 2(-0.85,0)
_RK73H1JTTD47R0F_+30 [mm] "KC00080BKP"
  rect 0.9x0.8 smd paste-0.9 mask+0: 1(0.85,0) 2(-0.85,0)
_RK73H1JTTD47R0F_+31 [mm] "KC00080BKP"
  rect 0.9x0.8 smd paste-0.9 mask+0: 1(0.85,0) 2(-0.85,0)
_RK73H1JTTD47R0F_+32 [mm] "KC00080BKP"
  rect 0.9x0.8 smd paste-0.9 mask+0: 1(0.85,0) 2(-0.85,0)
_RK73H1JTTD47R0F_+33 [mm] "KC00080BKP"
  rect 0.9x0.8 smd paste-0.9 mask+0: 1(0.85,0) 2(-0.85,0)
_RK73H1JTTD47R0F_+34 [mm] "KC00080BKP"
  rect 0.9x0.8 smd paste-0.9 mask+0: 1(0.85,0) 2(-0.85,0)
_RK73H1JTTD47R0F_+35 [mm] "KC00080BKP"
  rect 0.9x0.8 smd paste-0.9 mask+0: 1(0.85,0) 2(-0.85,0)
_RK73H1JTTD47R0F_+36 [mm] "KC00080BKP"
  rect 0.9x0.8 smd paste-0.9 mask+0: 1(0.85,0) 2(-0.85,0)
_RK73H1JTTD47R0F_+37 [mm] "KC00080BKP"
  rect 0.9x0.8 smd paste-0.9 mask+0: 1(0.85,0) 2(-0.85,0)
_RK73H1JTTD47R0F_+38 [mm] "KC00080BKP"
  rect 0.9x0.8 smd paste-0.9 mask+0: 1(0.85,0) 2(-0.85,0)
_RK73H1JTTD47R0F_+39 [mm] "KC00080BKP"
  rect 0.9x0.8 smd paste-0.9 mask+0: 1(0.85,0) 2(-0.85,0)
_RK73H1JTTD473F_ [mm] "KC00080BKP"
  rect 0.9x0.8 smd paste-0.9 mask+0: 1(0.85,0) 2(-0.85,0)
_RK73H1JTTD473F_+1 [mm] "KC00080BKP"
  rect 0.9x0.8 smd paste-0.9 mask+0: 1(0.85,0) 2(-0.85,0)
_RK73H1JTTD473F_+2 [mm] "KC00080BKP"
  rect 0.9x0.8 smd paste-0.9 mask+0: 1(0.85,0) 2(-0.85,0)
_RK73H1JTTD473F_+3 [mm] "KC00080BKP"
  rect 0.9x0.8 smd paste-0.9 mask+0: 1(0.85,0) 2(-0.85,0)
_RK73H1JTTD1001F_ [mm] "KC00080BKP"
  rect 0.9x0.8 smd paste-0.9 mask+0: 1(0.85,0) 2(-0.85,0)
_RK73H1JTTD1001F_+1 [mm] "KC00080BKP"
  rect 0.9x0.8 smd paste-0.9 mask+0: 1(0.85,0) 2(-0.85,0)
_RK73H1JTTD1001F_+2 [mm] "KC00080BKP"
  rect 0.9x0.8 smd paste-0.9 mask+0: 1(0.85,0) 2(-0.85,0)
_RK73H1JTTD1001F_+3 [mm] "KC00080BKP"
  rect 0.9x0.8 smd paste-0.9 mask+0: 1(0.85,0) 2(-0.85,0)
_RK73H1JTTD1001F_+4 [mm] "KC00080BKP"
  rect 0.9x0.8 smd paste-0.9 mask+0: 1(0.85,0) 2(-0.85,0)
_RK73H1JTTD1001F_+5 [mm] "KC00080BKP"
  rect 0.9x0.8 smd paste-0.9 mask+0: 1(0.85,0) 2(-0.85,0)
_RK73H1JTTD1001F_+6 [mm] "KC00080BKP"
  rect 0.9x0.8 smd paste-0.9 mask+0: 1(0.85,0) 2(-0.85,0)
_RK73H1JTTD1001F_+7 [mm] "KC00080BKP"
  rect 0.9x0.8 smd paste-0.9 mask+0: 1(0.85,0) 2(-0.85,0)
_RK73H1JTTD1001F_+8 [mm] "KC00080BKP"
  rect 0.9x0.8 smd paste-0.9 mask+0: 1(0.85,0) 2(-0.85,0)
_RK73H1JTTD1001F_+9 [mm] "KC00080BKP"
  rect 0.9x0.8 smd paste-0.9 mask+0: 1(0.85,0) 2(-0.85,0)
_RK73H1JTTD1001F_+10 [mm] "KC00080BKP"
  rect 0.9x0.8 smd paste-0.9 mask+0: 1(0.85,0) 2(-0.85,0)
_RK73H1JTTD1001F_+11 [mm] "KC00080BKP"
  rect 0.9x0.8 smd paste-0.9 mask+0: 1(0.85,0) 2(-0.85,0)
_RK73H1JTTD1001F_+12 [mm] "KC00080BKP"
  rect 0.9x0.8 smd paste-0.9 mask+0: 1(0.85,0) 2(-0.85,0)
_RK73H1JTTD1001F_+13 [mm] "KC00080BKP"
  rect 0.9x0.8 smd paste-0.9 mask+0: 1(0.85,0) 2(-0.85,0)
_RK73H1JTTD1001F_+14 [mm] "KC00080BKP"
  rect 0.9x0.8 smd paste-0.9 mask+0: 1(0.85,0) 2(-0.85,0)
_RK73H1JTTD1001F_+15 [mm] "KC00080BKP"
  rect 0.9x0.8 smd paste-0.9 mask+0: 1(0.85,0) 2(-0.85,0)
_RK73H1JTTD1001F_+16 [mm] "KC00080BKP"
  rect 0.9x0.8 smd paste-0.9 mask+0: 1(0.85,0) 2(-0.85,0)
_RK73H1JTTD1001F_+17 [mm] "KC00080BKP"
  rect 0.9x0.8 smd paste-0.9 mask+0: 1(0.85,0) 2(-0.85,0)
_RK73H1JTTD1001F_+18 [mm] "KC00080BKP"
  rect 0.9x0.8 smd paste-0.9 mask+0: 1(0.85,0) 2(-0.85,0)
_RK73H1JTTD1001F_+19 [mm] "KC00080BKP"
  rect 0.9x0.8 smd paste-0.9 mask+0: 1(0.85,0) 2(-0.85,0)
_RK73H1JTTD1001F_+20 [mm] "KC00080BKP"
  rect 0.9x0.8 smd paste-0.9 mask+0: 1(0.85,0) 2(-0.85,0)
_RK73H1JTTD1001F_+21 [mm] "KC00080BKP"
  rect 0.9x0.8 smd paste-0.9 mask+0: 1(0.85,0) 2(-0.85,0)
_RK73H1JTTD1001F_+22 [mm] "KC00080BKP"
  rect 0.9x0.8 smd paste-0.9 mask+0: 1(0.85,0) 2(-0.85,0)
_RK73H1JTTD1001F_+23 [mm] "KC00080BKP"
  rect 0.9x0.8 smd paste-0.9 mask+0: 1(0.85,0) 2(-0.85,0)
_RK73H1JTTD1001F_+24 [mm] "KC00080BKP"
  rect 0.9x0.8 smd paste-0.9 mask+0: 1(0.85,0) 2(-0.85,0)
_RK73H1JTTD1001F_+25 [mm] "KC00080BKP"
  rect 0.9x0.8 smd paste-0.9 mask+0: 1(0.85,0) 2(-0.85,0)
_RK73H1JTTD1001F_+26 [mm] "KC00080BKP"
  rect 0.9x0.8 smd paste-0.9 mask+0: 1(0.85,0) 2(-0.85,0)
_RK73H1JTTD1001F_+27 [mm] "KC00080BKP"
  rect 0.9x0.8 smd paste-0.9 mask+0: 1(0.85,0) 2(-0.85,0)
_RK73H1JTTD1001F_+28 [mm] "KC00080BKP"
  rect 0.9x0.8 smd paste-0.9 mask+0: 1(0.85,0) 2(-0.85,0)
_RK73H1JTTD1001F_+29 [mm] "KC00080BKP"
  rect 0.9x0.8 smd paste-0.9 mask+0: 1(0.85,0) 2(-0.85,0)
_RK73H1JTTD1001F_+30 [mm] "KC00080BKP"
  rect 0.9x0.8 smd paste-0.9 mask+0: 1(0.85,0) 2(-0.85,0)
_RK73H1JTTD1001F_+31 [mm] "KC00080BKP"
  rect 0.9x0.8 smd paste-0.9 mask+0: 1(0.85,0) 2(-0.85,0)
_RK73H1JTTD1001F_+32 [mm] "KC00080BKP"
  rect 0.9x0.8 smd paste-0.9 mask+0: 1(0.85,0) 2(-0.85,0)
_RK73H1JTTD1001F_+33 [mm] "KC00080BKP"
  rect 0.9x0.8 smd paste-0.9 mask+0: 1(0.85,0) 2(-0.85,0)
_RK73H1JTTD1001F_+34 [mm] "KC00080BKP"
  rect 0.9x0.8 smd paste-0.9 mask+0: 1(0.85,0) 2(-0.85,0)
_RK73H1JTTD1001F_+35 [mm] "KC00080BKP"
  rect 0.9x0.8 smd paste-0.9 mask+0: 1(0.85,0) 2(-0.85,0)
_RK73H1JTTD1001F_+36 [mm] "KC00080BKP"
  rect 0.9x0.8 smd paste-0.9 mask+0: 1(0.85,0) 2(-0.85,0)
_RK73H1JTTD1001F_+37 [mm] "KC00080BKP"
  rect 0.9x0.8 smd paste-0.9 mask+0: 1(0.85,0) 2(-0.85,0)
_RK73H1JTTD1001F_+38 [mm] "KC00080BKP"
  rect 0.9x0.8 smd paste-0.9 mask+0: 1(0.85,0) 2(-0.85,0)
_RK73H1JTTD1001F_+39 [mm] "KC00080BKP"
  rect 0.9x0.8 smd paste-0.9 mask+0: 1(0.85,0) 2(-0.85,0)
_RK73H1JTTD1001F_+40 [mm] "KC00080BKP"
  rect 0.9x0.8 smd paste-0.9 mask+0: 1(0.85,0) 2(-0.85,0)
_RK73H1JTTD1001F_+41 [mm] "KC00080BKP"
  rect 0.9x0.8 smd paste-0.9 mask+0: 1(0.85,0) 2(-0.85,0)
_RK73H1JTTD1001F_+42 [mm] "KC00080BKP"
  rect 0.9x0.8 smd paste-0.9 mask+0: 1(0.85,0) 2(-0.85,0)
_RK73H1JTTD1001F_+43 [mm] "KC00080BKP"
  rect 0.9x0.8 smd paste-0.9 mask+0: 1(0.85,0) 2(-0.85,0)
_RK73H1JTTD1001F_+44 [mm] "KC00080BKP"
  rect 0.9x0.8 smd paste-0.9 mask+0: 1(0.85,0) 2(-0.85,0)
_RK73H1JTTD1001F_+45 [mm] "KC00080BKP"
  rect 0.9x0.8 smd paste-0.9 mask+0: 1(0.85,0) 2(-0.85,0)
_RK73H1JTTD1001F_+46 [mm] "KC00080BKP"
  rect 0.9x0.8 smd paste-0.9 mask+0: 1(0.85,0) 2(-0.85,0)
_RK73H1JTTD1001F_+47 [mm] "KC00080BKP"
  rect 0.9x0.8 smd paste-0.9 mask+0: 1(0.85,0) 2(-0.85,0)
_RK73H1JTTD1001F_+48 [mm] "KC00080BKP"
  rect 0.9x0.8 smd paste-0.9 mask+0: 1(0.85,0) 2(-0.85,0)
_RK73H1JTTD1001F_+49 [mm] "KC00080BKP"
  rect 0.9x0.8 smd paste-0.9 mask+0: 1(0.85,0) 2(-0.85,0)
_RK73H1JTTD1001F_+50 [mm] "KC00080BKP"
  rect 0.9x0.8 smd paste-0.9 mask+0: 1(0.85,0) 2(-0.85,0)
_RK73H1JTTD1001F_+51 [mm] "KC00080BKP"
  rect 0.9x0.8 smd paste-0.9 mask+0: 1(0.85,0) 2(-0.85,0)
_RK73H1JTTD1001F_+52 [mm] "KC00080BKP"
  rect 0.9x0.8 smd paste-0.9 mask+0: 1(0.85,0) 2(-0.85,0)
_RK73H1JTTD1001F_+53 [mm] "KC00080BKP"
  rect 0.9x0.8 smd paste-0.9 mask+0: 1(0.85,0) 2(-0.85,0)
_RK73H1JTTD1001F_+54 [mm] "KC00080BKP"
  rect 0.9x0.8 smd paste-0.9 mask+0: 1(0.85,0) 2(-0.85,0)
_RK73H1JTTD1001F_+55 [mm] "KC00080BKP"
  rect 0.9x0.8 smd paste-0.9 mask+0: 1(0.85,0) 2(-0.85,0)
_RK73H1JTTD1001F_+56 [mm] "KC00080BKP"
  rect 0.9x0.8 smd paste-0.9 mask+0: 1(0.85,0) 2(-0.85,0)
_RK73H1JTTD1001F_+57 [mm] "KC00080BKP"
  rect 0.9x0.8 smd paste-0.9 mask+0: 1(0.85,0) 2(-0.85,0)
_RK73H1JTTD1001F_+58 [mm] "KC00080BKP"
  rect 0.9x0.8 smd paste-0.9 mask+0: 1(0.85,0) 2(-0.85,0)
_RK73H1JTTD1001F_+59 [mm] "KC00080BKP"
  rect 0.9x0.8 smd paste-0.9 mask+0: 1(0.85,0) 2(-0.85,0)
_RK73H1JTTD1001F_+60 [mm] "KC00080BKP"
  rect 0.9x0.8 smd paste-0.9 mask+0: 1(0.85,0) 2(-0.85,0)
_RK73H1JTTD1001F_+61 [mm] "KC00080BKP"
  rect 0.9x0.8 smd paste-0.9 mask+0: 1(0.85,0) 2(-0.85,0)
_RK73H1JTTD1001F_+62 [mm] "KC00080BKP"
  rect 0.9x0.8 smd paste-0.9 mask+0: 1(0.85,0) 2(-0.85,0)
_RK73H1JTTD1001F_+63 [mm] "KC00080BKP"
  rect 0.9x0.8 smd paste-0.9 mask+0: 1(0.85,0) 2(-0.85,0)
_RK73H1JTTD1001F_+64 [mm] "KC00080BKP"
  rect 0.9x0.8 smd paste-0.9 mask+0: 1(0.85,0) 2(-0.85,0)
_RK73H1JTTD1001F_+65 [mm] "KC00080BKP"
  rect 0.9x0.8 smd paste-0.9 mask+0: 1(0.85,0) 2(-0.85,0)
_RK73H1JTTD1001F_+66 [mm] "KC00080BKP"
  rect 0.9x0.8 smd paste-0.9 mask+0: 1(0.85,0) 2(-0.85,0)
_RK73H1JTTD1001F_+67 [mm] "KC00080BKP"
  rect 0.9x0.8 smd paste-0.9 mask+0: 1(0.85,0) 2(-0.85,0)
_RK73H1JTTD1001F_+68 [mm] "KC00080BKP"
  rect 0.9x0.8 smd paste-0.9 mask+0: 1(0.85,0) 2(-0.85,0)
_RK73H1JTTD1001F_+69 [mm] "KC00080BKP"
  rect 0.9x0.8 smd paste-0.9 mask+0: 1(0.85,0) 2(-0.85,0)
_RK73H1JTTD1001F_+70 [mm] "KC00080BKP"
  rect 0.9x0.8 smd paste-0.9 mask+0: 1(0.85,0) 2(-0.85,0)
_RK73H1JTTD1001F_+71 [mm] "KC00080BKP"
  rect 0.9x0.8 smd paste-0.9 mask+0: 1(0.85,0) 2(-0.85,0)
_RK73H1JTTD2202F_ [mm] "KC00080BKP"
  rect 0.9x0.8 smd paste-0.9 mask+0: 1(0.85,0) 2(-0.85,0)
_RK73H1JTTD2202F_+1 [mm] "KC00080BKP"
  rect 0.9x0.8 smd paste-0.9 mask+0: 1(0.85,0) 2(-0.85,0)
_RK73H1JTTD2202F_+2 [mm] "KC00080BKP"
  rect 0.9x0.8 smd paste-0.9 mask+0: 1(0.85,0) 2(-0.85,0)
_RK73H1JTTD2202F_+3 [mm] "KC00080BKP"
  rect 0.9x0.8 smd paste-0.9 mask+0: 1(0.85,0) 2(-0.85,0)
_RK73H1JTTD2202F_+4 [mm] "KC00080BKP"
  rect 0.9x0.8 smd paste-0.9 mask+0: 1(0.85,0) 2(-0.85,0)
_RK73H1JTTD2202F_+5 [mm] "KC00080BKP"
  rect 0.9x0.8 smd paste-0.9 mask+0: 1(0.85,0) 2(-0.85,0)
_RK73H1JTTD2202F_+6 [mm] "KC00080BKP"
  rect 0.9x0.8 smd paste-0.9 mask+0: 1(0.85,0) 2(-0.85,0)
_RK73H1JTTD2202F_+7 [mm] "KC00080BKP"
  rect 0.9x0.8 smd paste-0.9 mask+0: 1(0.85,0) 2(-0.85,0)
_RK73H1JTTD2202F_+8 [mm] "KC00080BKP"
  rect 0.9x0.8 smd paste-0.9 mask+0: 1(0.85,0) 2(-0.85,0)
_RK73H1JTTD2202F_+9 [mm] "KC00080BKP"
  rect 0.9x0.8 smd paste-0.9 mask+0: 1(0.85,0) 2(-0.85,0)
_RK73H1JTTD2202F_+10 [mm] "KC00080BKP"
  rect 0.9x0.8 smd paste-0.9 mask+0: 1(0.85,0) 2(-0.85,0)
_RK73H1JTTD2202F_+11 [mm] "KC00080BKP"
  rect 0.9x0.8 smd paste-0.9 mask+0: 1(0.85,0) 2(-0.85,0)
_RK73H1JTTD2202F_+12 [mm] "KC00080BKP"
  rect 0.9x0.8 smd paste-0.9 mask+0: 1(0.85,0) 2(-0.85,0)
_RK73H1JTTD2202F_+13 [mm] "KC00080BKP"
  rect 0.9x0.8 smd paste-0.9 mask+0: 1(0.85,0) 2(-0.85,0)
_RK73H1JTTD2202F_+14 [mm] "KC00080BKP"
  rect 0.9x0.8 smd paste-0.9 mask+0: 1(0.85,0) 2(-0.85,0)
_RK73H1JTTD2202F_+15 [mm] "KC00080BKP"
  rect 0.9x0.8 smd paste-0.9 mask+0: 1(0.85,0) 2(-0.85,0)
_RK73H1JTTD2202F_+16 [mm] "KC00080BKP"
  rect 0.9x0.8 smd paste-0.9 mask+0: 1(0.85,0) 2(-0.85,0)
_RK73H1JTTD2202F_+17 [mm] "KC00080BKP"
  rect 0.9x0.8 smd paste-0.9 mask+0: 1(0.85,0) 2(-0.85,0)
_RK73H1JTTD2202F_+18 [mm] "KC00080BKP"
  rect 0.9x0.8 smd paste-0.9 mask+0: 1(0.85,0) 2(-0.85,0)
_RK73H1JTTD2202F_+19 [mm] "KC00080BKP"
  rect 0.9x0.8 smd paste-0.9 mask+0: 1(0.85,0) 2(-0.85,0)
_RK73H1JTTD2202F_+20 [mm] "KC00080BKP"
  rect 0.9x0.8 smd paste-0.9 mask+0: 1(0.85,0) 2(-0.85,0)
_RK73H1JTTD2202F_+21 [mm] "KC00080BKP"
  rect 0.9x0.8 smd paste-0.9 mask+0: 1(0.85,0) 2(-0.85,0)
_RK73H1JTTD2202F_+22 [mm] "KC00080BKP"
  rect 0.9x0.8 smd paste-0.9 mask+0: 1(0.85,0) 2(-0.85,0)
_RK73H1JTTD2202F_+23 [mm] "KC00080BKP"
  rect 0.9x0.8 smd paste-0.9 mask+0: 1(0.85,0) 2(-0.85,0)
_RK73H1JTTD2701F_ [mm] "KC00080BKP"
  rect 0.9x0.8 smd paste-0.9 mask+0: 1(0.85,0) 2(-0.85,0)
_RK73H1JTTD2701F_+1 [mm] "KC00080BKP"
  rect 0.9x0.8 smd paste-0.9 mask+0: 1(0.85,0) 2(-0.85,0)
_RK73H1JTTD2701F_+2 [mm] "KC00080BKP"
  rect 0.9x0.8 smd paste-0.9 mask+0: 1(0.85,0) 2(-0.85,0)
_RK73H1JTTD2701F_+3 [mm] "KC00080BKP"
  rect 0.9x0.8 smd paste-0.9 mask+0: 1(0.85,0) 2(-0.85,0)
_RK73H1JTTD2701F_+4 [mm] "KC00080BKP"
  rect 0.9x0.8 smd paste-0.9 mask+0: 1(0.85,0) 2(-0.85,0)
_RK73H1JTTD2701F_+5 [mm] "KC00080BKP"
  rect 0.9x0.8 smd paste-0.9 mask+0: 1(0.85,0) 2(-0.85,0)
_RK73H1JTTD2701F_+6 [mm] "KC00080BKP"
  rect 0.9x0.8 smd paste-0.9 mask+0: 1(0.85,0) 2(-0.85,0)
_RK73H1JTTD2701F_+7 [mm] "KC00080BKP"
  rect 0.9x0.8 smd paste-0.9 mask+0: 1(0.85,0) 2(-0.85,0)
_RK73H1JTTD2701F_+8 [mm] "KC00080BKP"
  rect 0.9x0.8 smd paste-0.9 mask+0: 1(0.85,0) 2(-0.85,0)
_RK73H1JTTD2701F_+9 [mm] "KC00080BKP"
  rect 0.9x0.8 smd paste-0.9 mask+0: 1(0.85,0) 2(-0.85,0)
_RK73H1JTTD2701F_+10 [mm] "KC00080BKP"
  rect 0.9x0.8 smd paste-0.9 mask+0: 1(0.85,0) 2(-0.85,0)
_RK73H1JTTD2701F_+11 [mm] "KC00080BKP"
  rect 0.9x0.8 smd paste-0.9 mask+0: 1(0.85,0) 2(-0.85,0)
_RK73H1JTTD2701F_+12 [mm] "KC00080BKP"
  rect 0.9x0.8 smd paste-0.9 mask+0: 1(0.85,0) 2(-0.85,0)
_RK73H1JTTD2701F_+13 [mm] "KC00080BKP"
  rect 0.9x0.8 smd paste-0.9 mask+0: 1(0.85,0) 2(-0.85,0)
_RK73H1JTTD2701F_+14 [mm] "KC00080BKP"
  rect 0.9x0.8 smd paste-0.9 mask+0: 1(0.85,0) 2(-0.85,0)
_RK73H1JTTD2701F_+15 [mm] "KC00080BKP"
  rect 0.9x0.8 smd paste-0.9 mask+0: 1(0.85,0) 2(-0.85,0)
_RK73H1JTTD2701F_+16 [mm] "KC00080BKP"
  rect 0.9x0.8 smd paste-0.9 mask+0: 1(0.85,0) 2(-0.85,0)
_RK73H1JTTD2701F_+17 [mm] "KC00080BKP"
  rect 0.9x0.8 smd paste-0.9 mask+0: 1(0.85,0) 2(-0.85,0)
_RK73H1JTTD2701F_+18 [mm] "KC00080BKP"
  rect 0.9x0.8 smd paste-0.9 mask+0: 1(0.85,0) 2(-0.85,0)
_RK73H1JTTD2701F_+19 [mm] "KC00080BKP"
  rect 0.9x0.8 smd paste-0.9 mask+0: 1(0.85,0) 2(-0.85,0)
_RK73H1JTTD2701F_+20 [mm] "KC00080BKP"
  rect 0.9x0.8 smd paste-0.9 mask+0: 1(0.85,0) 2(-0.85,0)
_RK73H1JTTD2701F_+21 [mm] "KC00080BKP"
  rect 0.9x0.8 smd paste-0.9 mask+0: 1(0.85,0) 2(-0.85,0)
_RK73H1JTTD2701F_+22 [mm] "KC00080BKP"
  rect 0.9x0.8 smd paste-0.9 mask+0: 1(0.85,0) 2(-0.85,0)
_RK73H1JTTD2701F_+23 [mm] "KC00080BKP"
  rect 0.9x0.8 smd paste-0.9 mask+0: 1(0.85,0) 2(-0.85,0)
_RK73Z1JTTD_ [mm] "KC00080BKP"
  rect 0.9x0.8 smd paste-0.9 mask+0: 1(0.85,0) 2(-0.85,0)
_RK73Z1JTTD_+1 [mm] "KC00080BKP"
  rect 0.9x0.8 smd paste-0.9 mask+0: 1(0.85,0) 2(-0.85,0)
_RK73Z1JTTD_+2 [mm] "KC00080BKP"
  rect 0.9x0.8 smd paste-0.9 mask+0: 1(0.85,0) 2(-0.85,0)
_RK73Z1JTTD_+3 [mm] "KC00080BKP"
  rect 0.9x0.8 smd paste-0.9 mask+0: 1(0.85,0) 2(-0.85,0)
_RK73Z1JTTD_+4 [mm] "KC00080BKP"
  rect 0.9x0.8 smd paste-0.9 mask+0: 1(0.85,0) 2(-0.85,0)
_RK73Z1JTTD_+5 [mm] "KC00080BKP"
  rect 0.9x0.8 smd paste-0.9 mask+0: 1(0.85,0) 2(-0.85,0)
_RK73Z1JTTD_+6 [mm] "KC00080BKP"
  rect 0.9x0.8 smd paste-0.9 mask+0: 1(0.85,0) 2(-0.85,0)
_RK73Z1JTTD_+7 [mm] "KC00080BKP"
  rect 0.9x0.8 smd paste-0.9 mask+0: 1(0.85,0) 2(-0.85,0)
_RK73Z1JTTD_+8 [mm] "KC00080BKP"
  rect 0.9x0.8 smd paste-0.9 mask+0: 1(0.85,0) 2(-0.85,0)
_RK73Z1JTTD_+9 [mm] "KC00080BKP"
  rect 0.9x0.8 smd paste-0.9 mask+0: 1(0.85,0) 2(-0.85,0)
_RK73Z1JTTD_+10 [mm] "KC00080BKP"
  rect 0.9x0.8 smd paste-0.9 mask+0: 1(0.85,0) 2(-0.85,0)
_RK73Z1JTTD_+11 [mm] "KC00080BKP"
  rect 0.9x0.8 smd paste-0.9 mask+0: 1(0.85,0) 2(-0.85,0)
_RK73Z1JTTD_+12 [mm] "KC00080BKP"
  rect 0.9x0.8 smd paste-0.9 mask+0: 1(0.85,0) 2(-0.85,0)
_RK73Z1JTTD_+13 [mm] "KC00080BKP"
  rect 0.9x0.8 smd paste-0.9 mask+0: 1(0.85,0) 2(-0.85,0)
_RK73Z1JTTD_+14 [mm] "KC00080BKP"
  rect 0.9x0.8 smd paste-0.9 mask+0: 1(0.85,0) 2(-0.85,0)
_RK73Z1JTTD_+15 [mm] "KC00080BKP"
  rect 0.9x0.8 smd paste-0.9 mask+0: 1(0.85,0) 2(-0.85,0)
_RK73Z1JTTD_+16 [mm] "KC00080BKP"
  rect 0.9x0.8 smd paste-0.9 mask+0: 1(0.85,0) 2(-0.85,0)
_RK73Z1JTTD_+17 [mm] "KC00080BKP"
  rect 0.9x0.8 smd paste-0.9 mask+0: 1(0.85,0) 2(-0.85,0)
_RK73Z1JTTD_+18 [mm] "KC00080BKP"
  rect 0.9x0.8 smd paste-0.9 mask+0: 1(0.85,0) 2(-0.85,0)
_RK73Z1JTTD_+19 [mm] "KC00080BKP"
  rect 0.9x0.8 smd paste-0.9 mask+0: 1(0.85,0) 2(-0.85,0)
_RK73Z1JTTD_+20 [mm] "KC00080BKP"
  rect 0.9x0.8 smd paste-0.9 mask+0: 1(0.85,0) 2(-0.85,0)
_RK73Z1JTTD_+21 [mm] "KC00080BKP"
  rect 0.9x0.8 smd paste-0.9 mask+0: 1(0.85,0) 2(-0.85,0)
_RK73Z1JTTD_+22 [mm] "KC00080BKP"
  rect 0.9x0.8 smd paste-0.9 mask+0: 1(0.85,0) 2(-0.85,0)
_RK73Z1JTTD_+23 [mm] "KC00080BKP"
  rect 0.9x0.8 smd paste-0.9 mask+0: 1(0.85,0) 2(-0.85,0)
_RN1907_ [mm] "KC00080BKP"
  rect 0.45x1.05 smd paste-1.05 mask+0: 1(0.65,1.025) 2(0,1.025) 3(-0.65,1.025) 4(-0.65,-1.025) 5(0,-1.025) 6(0.65,-1.025)
_RN1907_+1 [mm] "KC00080BKP"
  rect 0.45x1.05 smd paste-1.05 mask+0: 1(0.65,1.025) 2(0,1.025) 3(-0.65,1.025) 4(-0.65,-1.025) 5(0,-1.025) 6(0.65,-1.025)
_RN1907_+2 [mm] "KC00080BKP"
  rect 0.45x1.05 smd paste-1.05 mask+0: 1(0.65,1.025) 2(0,1.025) 3(-0.65,1.025) 4(-0.65,-1.025) 5(0,-1.025) 6(0.65,-1.025)
_RN1907_+3 [mm] "KC00080BKP"
  rect 0.45x1.05 smd paste-1.05 mask+0: 1(0.65,1.025) 2(0,1.025) 3(-0.65,1.025) 4(-0.65,-1.025) 5(0,-1.025) 6(0.65,-1.025)
_RN1907_+4 [mm] "KC00080BKP"
  rect 0.45x1.05 smd paste-1.05 mask+0: 1(0.65,1.025) 2(0,1.025) 3(-0.65,1.025) 4(-0.65,-1.025) 5(0,-1.025) 6(0.65,-1.025)
_RN1907_+5 [mm] "KC00080BKP"
  rect 0.45x1.05 smd paste-1.05 mask+0: 1(0.65,1.025) 2(0,1.025) 3(-0.65,1.025) 4(-0.65,-1.025) 5(0,-1.025) 6(0.65,-1.025)
_RN1907_+6 [mm] "KC00080BKP"
  rect 0.45x1.05 smd paste-1.05 mask+0: 1(0.65,1.025) 2(0,1.025) 3(-0.65,1.025) 4(-0.65,-1.025) 5(0,-1.025) 6(0.65,-1.025)
_RN1907_+7 [mm] "KC00080BKP"
  rect 0.45x1.05 smd paste-1.05 mask+0: 1(0.65,1.025) 2(0,1.025) 3(-0.65,1.025) 4(-0.65,-1.025) 5(0,-1.025) 6(0.65,-1.025)
_RN4907_ [mm] "KC00080BKP"
  rect 0.45x1.05 smd paste-1.05 mask+0: 1(-0.65,-1.025) 2(0,-1.025) 3(0.65,-1.025) 4(0.65,1.025) 5(0,1.025) 6(-0.65,1.025)
_RN4907_+1 [mm] "KC00080BKP"
  rect 0.45x1.05 smd paste-1.05 mask+0: 1(-0.65,-1.025) 2(0,-1.025) 3(0.65,-1.025) 4(0.65,1.025) 5(0,1.025) 6(-0.65,1.025)
_RN4907_+2 [mm] "KC00080BKP"
  rect 0.45x1.05 smd paste-1.05 mask+0: 1(-0.65,-1.025) 2(0,-1.025) 3(0.65,-1.025) 4(0.65,1.025) 5(0,1.025) 6(-0.65,1.025)
_RN4907_+3 [mm] "KC00080BKP"
  rect 0.45x1.05 smd paste-1.05 mask+0: 1(-0.65,-1.025) 2(0,-1.025) 3(0.65,-1.025) 4(0.65,1.025) 5(0,1.025) 6(-0.65,1.025)
_RN4907_+4 [mm] "KC00080BKP"
  rect 0.45x1.05 smd paste-1.05 mask+0: 1(-0.65,-1.025) 2(0,-1.025) 3(0.65,-1.025) 4(0.65,1.025) 5(0,1.025) 6(-0.65,1.025)
_RN4907_+5 [mm] "KC00080BKP"
  rect 0.45x1.05 smd paste-1.05 mask+0: 1(-0.65,-1.025) 2(0,-1.025) 3(0.65,-1.025) 4(0.65,1.025) 5(0,1.025) 6(-0.65,1.025)
_RN4907_+6 [mm] "KC00080BKP"
  rect 0.45x1.05 smd paste-1.05 mask+0: 1(-0.65,-1.025) 2(0,-1.025) 3(0.65,-1.025) 4(0.65,1.025) 5(0,1.025) 6(-0.65,1.025)
_RN4907_+7 [mm] "KC00080BKP"
  rect 0.45x1.05 smd paste-1.05 mask+0: 1(-0.65,-1.025) 2(0,-1.025) 3(0.65,-1.025) 4(0.65,1.025) 5(0,1.025) 6(-0.65,1.025)
_RN4907_+8 [mm] "KC00080BKP"
  rect 0.45x1.05 smd paste-1.05 mask+0: 1(-0.65,-1.025) 2(0,-1.025) 3(0.65,-1.025) 4(0.65,1.025) 5(0,1.025) 6(-0.65,1.025)
_RN4907_+9 [mm] "KC00080BKP"
  rect 0.45x1.05 smd paste-1.05 mask+0: 1(-0.65,-1.025) 2(0,-1.025) 3(0.65,-1.025) 4(0.65,1.025) 5(0,1.025) 6(-0.65,1.025)
_RN4907_+10 [mm] "KC00080BKP"
  rect 0.45x1.05 smd paste-1.05 mask+0: 1(-0.65,-1.025) 2(0,-1.025) 3(0.65,-1.025) 4(0.65,1.025) 5(0,1.025) 6(-0.65,1.025)
_RN4907_+11 [mm] "KC00080BKP"
  rect 0.45x1.05 smd paste-1.05 mask+0: 1(-0.65,-1.025) 2(0,-1.025) 3(0.65,-1.025) 4(0.65,1.025) 5(0,1.025) 6(-0.65,1.025)
_RN4907_+12 [mm] "KC00080BKP"
  rect 0.45x1.05 smd paste-1.05 mask+0: 1(-0.65,-1.025) 2(0,-1.025) 3(0.65,-1.025) 4(0.65,1.025) 5(0,1.025) 6(-0.65,1.025)
_RN4907_+13 [mm] "KC00080BKP"
  rect 0.45x1.05 smd paste-1.05 mask+0: 1(-0.65,-1.025) 2(0,-1.025) 3(0.65,-1.025) 4(0.65,1.025) 5(0,1.025) 6(-0.65,1.025)
_RN4907_+14 [mm] "KC00080BKP"
  rect 0.45x1.05 smd paste-1.05 mask+0: 1(-0.65,-1.025) 2(0,-1.025) 3(0.65,-1.025) 4(0.65,1.025) 5(0,1.025) 6(-0.65,1.025)
_RN4907_+15 [mm] "KC00080BKP"
  rect 0.45x1.05 smd paste-1.05 mask+0: 1(-0.65,-1.025) 2(0,-1.025) 3(0.65,-1.025) 4(0.65,1.025) 5(0,1.025) 6(-0.65,1.025)
_RN4907_+16 [mm] "KC00080BKP"
  rect 0.45x1.05 smd paste-1.05 mask+0: 1(-0.65,-1.025) 2(0,-1.025) 3(0.65,-1.025) 4(0.65,1.025) 5(0,1.025) 6(-0.65,1.025)
_RN4907_+17 [mm] "KC00080BKP"
  rect 0.45x1.05 smd paste-1.05 mask+0: 1(-0.65,-1.025) 2(0,-1.025) 3(0.65,-1.025) 4(0.65,1.025) 5(0,1.025) 6(-0.65,1.025)
_RN4907_+18 [mm] "KC00080BKP"
  rect 0.45x1.05 smd paste-1.05 mask+0: 1(-0.65,-1.025) 2(0,-1.025) 3(0.65,-1.025) 4(0.65,1.025) 5(0,1.025) 6(-0.65,1.025)
_RN4907_+19 [mm] "KC00080BKP"
  rect 0.45x1.05 smd paste-1.05 mask+0: 1(-0.65,-1.025) 2(0,-1.025) 3(0.65,-1.025) 4(0.65,1.025) 5(0,1.025) 6(-0.65,1.025)
_RN4907_+20 [mm] "KC00080BKP"
  rect 0.45x1.05 smd paste-1.05 mask+0: 1(-0.65,-1.025) 2(0,-1.025) 3(0.65,-1.025) 4(0.65,1.025) 5(0,1.025) 6(-0.65,1.025)
_RN4907_+21 [mm] "KC00080BKP"
  rect 0.45x1.05 smd paste-1.05 mask+0: 1(-0.65,-1.025) 2(0,-1.025) 3(0.65,-1.025) 4(0.65,1.025) 5(0,1.025) 6(-0.65,1.025)
_RN4907_+22 [mm] "KC00080BKP"
  rect 0.45x1.05 smd paste-1.05 mask+0: 1(-0.65,-1.025) 2(0,-1.025) 3(0.65,-1.025) 4(0.65,1.025) 5(0,1.025) 6(-0.65,1.025)
_RN4907_+23 [mm] "KC00080BKP"
  rect 0.45x1.05 smd paste-1.05 mask+0: 1(-0.65,-1.025) 2(0,-1.025) 3(0.65,-1.025) 4(0.65,1.025) 5(0,1.025) 6(-0.65,1.025)
_RS73F1JTTD39R0F_ [mm] "KC00080BKP"
  rect 0.9x0.8 smd paste-0.9 mask+0: 1(0.85,0) 2(-0.85,0)
_RS73F1JTTD47R0F_ [mm] "KC00080BKP"
  rect 0.9x0.8 smd paste-0.9 mask+0: 1(-0.85,0) 2(0.85,0)
_RS73F1JTTD47R0F_+1 [mm] "KC00080BKP"
  rect 0.9x0.8 smd paste-0.9 mask+0: 1(-0.85,0) 2(0.85,0)
_RS73F1JTTD47R0F_+2 [mm] "KC00080BKP"
  rect 0.9x0.8 smd paste-0.9 mask+0: 1(-0.85,0) 2(0.85,0)
_RS73F1JTTD47R0F_+3 [mm] "KC00080BKP"
  rect 0.9x0.8 smd paste-0.9 mask+0: 1(-0.85,0) 2(0.85,0)
_RS73F1JTTD47R0F_+4 [mm] "KC00080BKP"
  rect 0.9x0.8 smd paste-0.9 mask+0: 1(-0.85,0) 2(0.85,0)
_RS73F1JTTD47R0F_+5 [mm] "KC00080BKP"
  rect 0.9x0.8 smd paste-0.9 mask+0: 1(-0.85,0) 2(0.85,0)
_RS73F1JTTD47R0F_+6 [mm] "KC00080BKP"
  rect 0.9x0.8 smd paste-0.9 mask+0: 1(-0.85,0) 2(0.85,0)
_RS73F1JTTD47R0F_+7 [mm] "KC00080BKP"
  rect 0.9x0.8 smd paste-0.9 mask+0: 1(-0.85,0) 2(0.85,0)
_RS73F1JTTD1001D_ [mm] "KC00080BKP"
  rect 0.9x0.8 smd paste-0.9 mask+0: 1(-0.85,0) 2(0.85,0)
_RS73F1JTTD1002F_ [mm] "KC00080BKP"
  rect 0.9x0.8 smd paste-0.9 mask+0: 1(0.85,0) 2(-0.85,0)
_RS73F1JTTD1002F_+1 [mm] "KC00080BKP"
  rect 0.9x0.8 smd paste-0.9 mask+0: 1(0.85,0) 2(-0.85,0)
_RS73F1JTTD1002F_+2 [mm] "KC00080BKP"
  rect 0.9x0.8 smd paste-0.9 mask+0: 1(0.85,0) 2(-0.85,0)
_RS73F1JTTD1002F_+3 [mm] "KC00080BKP"
  rect 0.9x0.8 smd paste-0.9 mask+0: 1(0.85,0) 2(-0.85,0)
_RS73F1JTTD1002F_+4 [mm] "KC00080BKP"
  rect 0.9x0.8 smd paste-0.9 mask+0: 1(-0.85,0) 2(0.85,0)
_RS73F1JTTD1002F_+5 [mm] "KC00080BKP"
  rect 0.9x0.8 smd paste-0.9 mask+0: 1(0.85,0) 2(-0.85,0)
_RS73F1JTTD1002F_+6 [mm] "KC00080BKP"
  rect 0.9x0.8 smd paste-0.9 mask+0: 1(0.85,0) 2(-0.85,0)
_RS73F1JTTD1002F_+7 [mm] "KC00080BKP"
  rect 0.9x0.8 smd paste-0.9 mask+0: 1(0.85,0) 2(-0.85,0)
_RS73F1JTTD1002F_+8 [mm] "KC00080BKP"
  rect 0.9x0.8 smd paste-0.9 mask+0: 1(0.85,0) 2(-0.85,0)
_RS73F1JTTD1003F_ [mm] "KC00080BKP"
  rect 0.9x0.8 smd paste-0.9 mask+0: 1(0.85,0) 2(-0.85,0)
_RS73F1JTTD1202D_ [mm] "KC00080BKP"
  rect 0.9x0.8 smd paste-0.9 mask+0: 1(0.85,0) 2(-0.85,0)
_RS73F1JTTD1801D_ [mm] "KC00080BKP"
  rect 0.9x0.8 smd paste-0.9 mask+0: 1(0.85,0) 2(-0.85,0)
_RS73F1JTTD1802F_ [mm] "KC00080BKP"
  rect 0.9x0.8 smd paste-0.9 mask+0: 1(-0.85,0) 2(0.85,0)
_RS73F1JTTD1802F_+1 [mm] "KC00080BKP"
  rect 0.9x0.8 smd paste-0.9 mask+0: 1(0.85,0) 2(-0.85,0)
_RS73F1JTTD2003D_ [mm] "KC00080BKP"
  rect 0.9x0.8 smd paste-0.9 mask+0: 1(-0.85,0) 2(0.85,0)
_RS73F1JTTD2003D_+1 [mm] "KC00080BKP"
  rect 0.9x0.8 smd paste-0.9 mask+0: 1(0.85,0) 2(-0.85,0)
_RS73F1JTTD2402D_ [mm] "KC00080BKP"
  rect 0.9x0.8 smd paste-0.9 mask+0: 1(-0.85,0) 2(0.85,0)
_RS73F1JTTD2403D_ [mm] "KC00080BKP"
  rect 0.9x0.8 smd paste-0.9 mask+0: 1(-0.85,0) 2(0.85,0)
_RS73F1JTTD2702F_ [mm] "KC00080BKP"
  rect 0.9x0.8 smd paste-0.9 mask+0: 1(0.85,0) 2(-0.85,0)
_RS73F1JTTD3000F_ [mm] "KC00080BKP"
  rect 0.9x0.8 smd paste-0.9 mask+0: 1(0.85,0) 2(-0.85,0)
_RS73F1JTTD3303D_ [mm] "KC00080BKP"
  rect 0.9x0.8 smd paste-0.9 mask+0: 1(-0.85,0) 2(0.85,0)
_RS73F1JTTD3602D_ [mm] "KC00080BKP"
  rect 0.9x0.8 smd paste-0.9 mask+0: 1(-0.85,0) 2(0.85,0)
_RS73F1JTTD4303F_ [mm] "KC00080BKP"
  rect 0.9x0.8 smd paste-0.9 mask+0: 1(-0.85,0) 2(0.85,0)
_RS73F1JTTD4701F_ [mm] "KC00080BKP"
  rect 0.9x0.8 smd paste-0.9 mask+0: 1(0.85,0) 2(-0.85,0)
_RS73F1JTTD4701F_+1 [mm] "KC00080BKP"
  rect 0.9x0.8 smd paste-0.9 mask+0: 1(0.85,0) 2(-0.85,0)
_RS73F1JTTD4701F_+2 [mm] "KC00080BKP"
  rect 0.9x0.8 smd paste-0.9 mask+0: 1(0.85,0) 2(-0.85,0)
_RS73F1JTTD6801D_ [mm] "KC00080BKP"
  rect 0.9x0.8 smd paste-0.9 mask+0: 1(0.85,0) 2(-0.85,0)
_RS73F1JTTD7501D_ [mm] "KC00080BKP"
  rect 0.9x0.8 smd paste-0.9 mask+0: 1(-0.85,0) 2(0.85,0)
_RS73F1JTTD7502D_ [mm] "KC00080BKP"
  rect 0.9x0.8 smd paste-0.9 mask+0: 1(-0.85,0) 2(0.85,0)
_RS73G1JTTD1001F_ [mm] "KC00080BKP"
  rect 0.9x0.8 smd paste-0.9 mask+0: 1(-0.85,0) 2(0.85,0)
_RS73G1JTTD1001F_+1 [mm] "KC00080BKP"
  rect 0.9x0.8 smd paste-0.9 mask+0: 1(0.85,0) 2(-0.85,0)
_RS73G1JTTD1002F_ [mm] "KC00080BKP"
  rect 0.9x0.8 smd paste-0.9 mask+0: 1(-0.85,0) 2(0.85,0)
_RS73G1JTTD1002F_+1 [mm] "KC00080BKP"
  rect 0.9x0.8 smd paste-0.9 mask+0: 1(0.85,0) 2(-0.85,0)
_RS73G1JTTD1002F_+2 [mm] "KC00080BKP"
  rect 0.9x0.8 smd paste-0.9 mask+0: 1(0.85,0) 2(-0.85,0)
_RS73G1JTTD1002F_+3 [mm] "KC00080BKP"
  rect 0.9x0.8 smd paste-0.9 mask+0: 1(-0.85,0) 2(0.85,0)
_RS73G1JTTD1002F_+4 [mm] "KC00080BKP"
  rect 0.9x0.8 smd paste-0.9 mask+0: 1(-0.85,0) 2(0.85,0)
_RS73G1JTTD1002F_+5 [mm] "KC00080BKP"
  rect 0.9x0.8 smd paste-0.9 mask+0: 1(-0.85,0) 2(0.85,0)
_RS73G1JTTD1002F_+6 [mm] "KC00080BKP"
  rect 0.9x0.8 smd paste-0.9 mask+0: 1(-0.85,0) 2(0.85,0)
_RS73G1JTTD1002F_+7 [mm] "KC00080BKP"
  rect 0.9x0.8 smd paste-0.9 mask+0: 1(-0.85,0) 2(0.85,0)
_RS73G1JTTD1002F_+8 [mm] "KC00080BKP"
  rect 0.9x0.8 smd paste-0.9 mask+0: 1(-0.85,0) 2(0.85,0)
_RS73G1JTTD1002F_+9 [mm] "KC00080BKP"
  rect 0.9x0.8 smd paste-0.9 mask+0: 1(-0.85,0) 2(0.85,0)
_RS73G1JTTD1002F_+10 [mm] "KC00080BKP"
  rect 0.9x0.8 smd paste-0.9 mask+0: 1(-0.85,0) 2(0.85,0)
_RS73G1JTTD1002F_+11 [mm] "KC00080BKP"
  rect 0.9x0.8 smd paste-0.9 mask+0: 1(-0.85,0) 2(0.85,0)
_RS73G1JTTD1002F_+12 [mm] "KC00080BKP"
  rect 0.9x0.8 smd paste-0.9 mask+0: 1(-0.85,0) 2(0.85,0)
_RS73G1JTTD1002F_+13 [mm] "KC00080BKP"
  rect 0.9x0.8 smd paste-0.9 mask+0: 1(0.85,0) 2(-0.85,0)
_RS73G1JTTD1002F_+14 [mm] "KC00080BKP"
  rect 0.9x0.8 smd paste-0.9 mask+0: 1(0.85,0) 2(-0.85,0)
_RS73G1JTTD1002F_+15 [mm] "KC00080BKP"
  rect 0.9x0.8 smd paste-0.9 mask+0: 1(0.85,0) 2(-0.85,0)
_RS73G1JTTD1002F_+16 [mm] "KC00080BKP"
  rect 0.9x0.8 smd paste-0.9 mask+0: 1(0.85,0) 2(-0.85,0)
_RS73G1JTTD1002F_+17 [mm] "KC00080BKP"
  rect 0.9x0.8 smd paste-0.9 mask+0: 1(0.85,0) 2(-0.85,0)
_RS73G1JTTD1002F_+18 [mm] "KC00080BKP"
  rect 0.9x0.8 smd paste-0.9 mask+0: 1(0.85,0) 2(-0.85,0)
